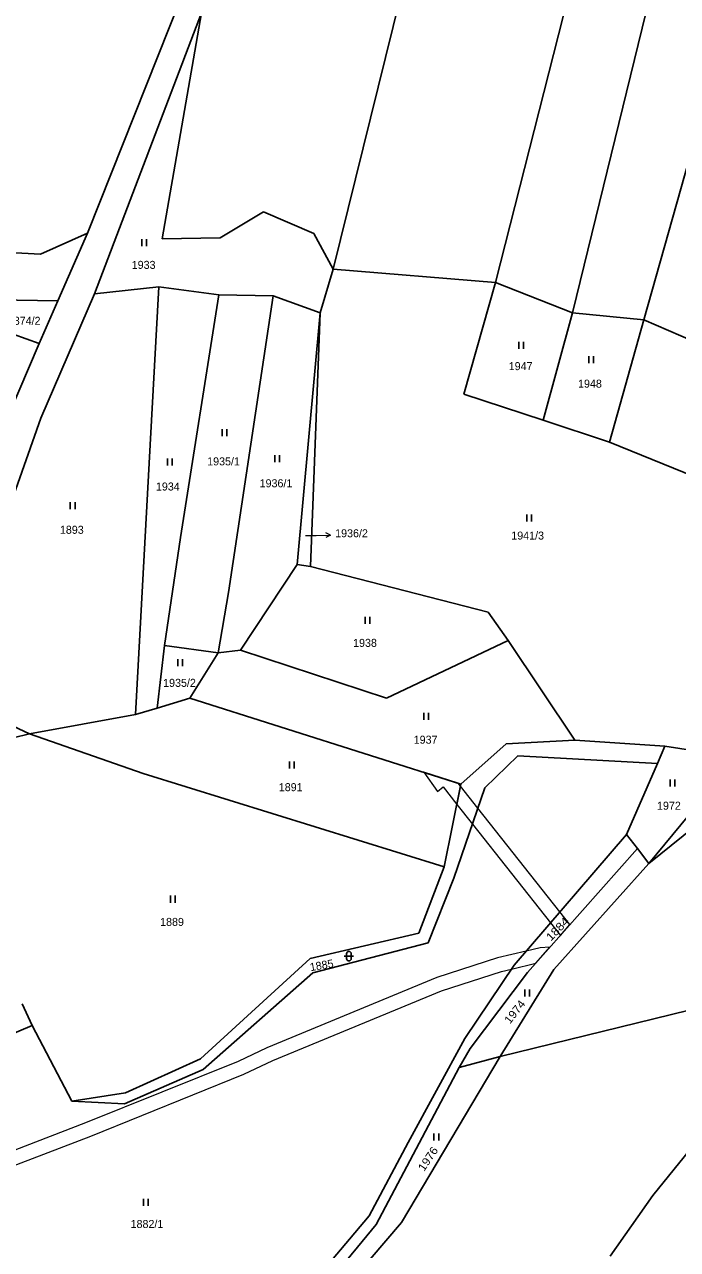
# Model space of a CAD drawing. Extents: x -820420 to -815896, y -1105820 to -1103643.
# Drawn here: x -817959 to -817820.3, y -1105443.7 to -1105183.5 of the extents above; entities that cross this region are included whole.
import ezdxf
from ezdxf.enums import TextEntityAlignment as Align

# ---------------------------------------------------------------- set-up
doc = ezdxf.new("R2010")
doc.units = 0
doc.header["$LTSCALE"] = 0.68
for name, color, linetype, lineweight in [('1', 7, 'Continuous', 25), ('13', 7, 'Continuous', 13), ('3', 7, 'Continuous', 25), ('7', 7, 'Continuous', 13)]:
    doc.layers.add(name, color=color, linetype=linetype, lineweight=lineweight)
doc.layers.add('2', color=7, linetype='Continuous')

msp = doc.modelspace()

# ---------------------------------------------------------------- linework, layer by layer
at = {"layer": '1'}
for p, q in [((-817869.71, -1105139.34), (-817893.45, -1105235.53)), ((-817911.24, -1105141.23), (-817945.61, -1105227.86)), ((-817821.32, -1105157.54), (-817842.63, -1105244.78)), ((-817858.96, -1105238.36), (-817841.26, -1105168.5)), ((-817944.12, -1105240.74), (-817921.42, -1105181.08)), ((-817921.42, -1105181.08), (-817929.76, -1105229.05)), ((-817827.46, -1105246.28), (-817810.28, -1105185.18)), ((-817917.43, -1105228.83), (-817908.24, -1105223.37)), ((-817908.24, -1105223.37), (-817897.54, -1105227.95)), ((-817955.63, -1105232.32), (-817945.61, -1105227.86)), ((-817945.61, -1105227.86), (-817951.93, -1105242.22)), ((-817929.76, -1105229.05), (-817917.43, -1105228.83)), ((-817897.54, -1105227.95), (-817893.45, -1105235.53)), ((-817973.59, -1105231.41), (-817955.63, -1105232.32)), ((-817893.45, -1105235.53), (-817896.18, -1105244.78)), ((-817893.45, -1105235.53), (-817858.96, -1105238.36)), ((-817930.44, -1105239.25), (-817944.12, -1105240.74)), ((-817932.31, -1105272.84), (-817930.44, -1105239.25)), ((-817917.7, -1105240.97), (-817930.44, -1105239.25)), ((-817865.72, -1105262.1), (-817858.96, -1105238.36)), ((-817858.96, -1105238.36), (-817842.63, -1105244.78)), ((-817951.93, -1105242.22), (-817984, -1105241.67)), ((-817955.85, -1105251.33), (-817951.93, -1105242.22)), ((-817955.55, -1105267.18), (-817944.12, -1105240.74)), ((-817917.7, -1105240.97), (-817925.86, -1105292.51)), ((-817906.21, -1105241.19), (-817917.7, -1105240.97)), ((-817906.21, -1105241.19), (-817915.66, -1105304.18)), ((-817896.18, -1105244.78), (-817906.21, -1105241.19)), ((-817901.09, -1105298.27), (-817896.18, -1105244.78)), ((-817898.25, -1105298.66), (-817896.18, -1105244.78)), ((-817842.63, -1105244.78), (-817848.88, -1105267.62)), ((-817842.63, -1105244.78), (-817827.46, -1105246.28)), ((-817827.46, -1105246.28), (-817834.79, -1105272.23)), ((-817827.46, -1105246.28), (-817795.47, -1105260.25)), ((-817964.22, -1105248.36), (-817955.85, -1105251.33)), ((-817964.57, -1105271.58), (-817955.85, -1105251.33)), ((-817848.88, -1105267.62), (-817865.72, -1105262.1)), ((-817955.55, -1105267.18), (-817968.42, -1105303.73)), ((-817834.79, -1105272.23), (-817848.88, -1105267.62)), ((-817935.41, -1105330.1), (-817932.31, -1105272.84)), ((-817804.94, -1105284.43), (-817834.79, -1105272.23)), ((-817925.86, -1105292.51), (-817929.3, -1105315.45)), ((-817913.14, -1105316.48), (-817901.09, -1105298.27)), ((-817898.25, -1105298.66), (-817901.09, -1105298.27)), ((-817898.25, -1105298.66), (-817860.52, -1105308.36)), ((-817915.66, -1105304.18), (-817917.89, -1105316.99)), ((-817860.52, -1105308.36), (-817856.31, -1105314.36)), ((-817856.31, -1105314.36), (-817882.12, -1105326.61)), ((-817856.31, -1105314.36), (-817842.12, -1105335.58)), ((-817929.3, -1105315.45), (-817930.79, -1105328.75)), ((-817929.3, -1105315.45), (-817917.89, -1105316.99)), ((-817917.89, -1105316.99), (-817923.89, -1105326.62)), ((-817917.89, -1105316.99), (-817913.14, -1105316.48)), ((-817882.12, -1105326.61), (-817913.14, -1105316.48)), ((-817923.89, -1105326.62), (-817930.79, -1105328.75)), ((-817866.31, -1105344.9), (-817923.89, -1105326.62)), ((-817957.96, -1105334.24), (-817968.34, -1105329.29)), ((-817935.41, -1105330.1), (-817957.96, -1105334.24)), ((-817930.79, -1105328.75), (-817935.41, -1105330.1)), ((-817977.63, -1105338.91), (-817957.96, -1105334.24)), ((-817957.96, -1105334.24), (-817933.78, -1105342.62)), ((-817856.74, -1105336.31), (-817842.12, -1105335.58)), ((-817842.12, -1105335.58), (-817823, -1105336.84)), ((-817866.31, -1105344.9), (-817856.74, -1105336.31)), ((-817797.31, -1105338.32), (-817826.4, -1105361.74)), ((-817824.6, -1105340.53), (-817823, -1105336.84)), ((-817823, -1105336.84), (-817812.7, -1105338.43)), ((-817854.26, -1105338.88), (-817861.26, -1105345.68)), ((-817824.6, -1105340.53), (-817854.26, -1105338.88)), ((-817831.13, -1105355.59), (-817824.6, -1105340.53)), ((-817933.78, -1105342.62), (-817869.85, -1105362.5)), ((-817869.85, -1105362.5), (-817866.31, -1105344.9)), ((-817861.26, -1105345.68), (-817867.79, -1105364.87)), ((-817814.49, -1105347.38), (-817826.4, -1105361.74)), ((-817831.13, -1105355.59), (-817855.04, -1105383.35)), ((-817828.85, -1105358.55), (-817831.13, -1105355.59)), ((-817852.2, -1105384.94), (-817828.85, -1105358.55)), ((-817826.4, -1105361.74), (-817828.85, -1105358.55)), ((-817846.59, -1105384.28), (-817826.4, -1105361.74)), ((-817875.28, -1105376.54), (-817869.85, -1105362.5)), ((-817867.79, -1105364.87), (-817873.31, -1105378.62)), ((-817898.34, -1105381.95), (-817875.28, -1105376.54)), ((-817873.31, -1105378.62), (-817897.8, -1105384.97)), ((-817921.6, -1105403.24), (-817898.34, -1105381.95)), ((-817897.8, -1105384.97), (-817921.06, -1105405.53)), ((-817855.04, -1105383.35), (-817865.52, -1105398.91)), ((-817864.33, -1105401.03), (-817852.2, -1105384.94)), ((-817782.25, -1105384.13), (-817857.97, -1105402.72)), ((-817857.97, -1105402.72), (-817846.59, -1105384.28)), ((-817959.52, -1105391.55), (-817957.4, -1105396.2)), ((-817970.34, -1105401.67), (-817957.4, -1105396.2)), ((-817957.4, -1105396.2), (-817948.98, -1105412.24)), ((-817865.52, -1105398.91), (-817877.52, -1105421.02)), ((-817866.7, -1105405.12), (-817864.33, -1105401.03)), ((-817937.55, -1105410.45), (-817921.6, -1105403.24)), ((-817857.97, -1105402.72), (-817878.93, -1105438.02)), ((-817857.97, -1105402.72), (-817866.7, -1105405.12)), ((-817921.06, -1105405.53), (-817937.76, -1105412.81)), ((-817884.31, -1105438.47), (-817866.7, -1105405.12)), ((-817948.98, -1105412.24), (-817937.55, -1105410.45)), ((-817825.59, -1105432.28), (-817807.78, -1105410.27)), ((-817937.76, -1105412.81), (-817948.98, -1105412.24)), ((-817877.52, -1105421.02), (-817885.84, -1105436.6)), ((-817834.63, -1105445.18), (-817825.59, -1105432.28)), ((-817885.84, -1105436.6), (-817905.34, -1105459.71)), ((-817913.51, -1105478.26), (-817878.93, -1105438.02)), ((-817902.19, -1105460), (-817884.31, -1105438.47))]:
    msp.add_line(p, q, dxfattribs=at)
at = {"layer": '13'}
for points in [[(-817871.27, -1105346.43), (-817870.1, -1105345.5), (-817867.18, -1105349.2), (-817866.4, -1105345.34), (-817866.9, -1105344.71), (-817874.22, -1105342.39)], [(-817847.3, -1105374.37), (-817845.2, -1105377.03), (-817843.18, -1105374.75), (-817845.31, -1105372.05), (-817862.73, -1105349.99), (-817866.4, -1105345.34), (-817867.18, -1105349.2), (-817863.88, -1105353.38)], [(-817906.26, -1105403.62), (-817870.42, -1105388.81), (-817857.72, -1105384.7), (-817855.6, -1105384.19), (-817850.44, -1105382.95), (-817847.44, -1105379.56), (-817849.48, -1105379.64), (-817852.45, -1105380.35), (-817858.54, -1105381.8), (-817871.44, -1105385.99), (-817907.52, -1105400.9), (-817913.62, -1105403.79), (-817946.01, -1105416.87), (-817970.85, -1105426.37), (-817990.71, -1105433.53), (-817989.76, -1105436.38), (-817969.79, -1105429.17), (-817944.93, -1105419.67), (-817912.4, -1105406.53)]]:
    msp.add_lwpolyline(points, close=True, dxfattribs=at)
at = {"layer": '3'}
for p, q in [((-817934.081, -1105230.62), (-817934.081, -1105229.12)), ((-817933.08, -1105230.62), (-817933.08, -1105229.12)), ((-817854.041, -1105252.45), (-817854.041, -1105250.95)), ((-817853.04, -1105252.45), (-817853.04, -1105250.95)), ((-817839.191, -1105255.51), (-817839.191, -1105254.01)), ((-817838.19, -1105255.51), (-817838.19, -1105254.01)), ((-817917.001, -1105270.97), (-817917.001, -1105269.47)), ((-817916, -1105270.97), (-817916, -1105269.47)), ((-817928.611, -1105277.24), (-817928.611, -1105275.74)), ((-817927.61, -1105277.24), (-817927.61, -1105275.74)), ((-817905.861, -1105276.54), (-817905.861, -1105275.04)), ((-817904.86, -1105276.54), (-817904.86, -1105275.04)), ((-817949.271, -1105286.53), (-817949.271, -1105285.03)), ((-817948.27, -1105286.53), (-817948.27, -1105285.03)), ((-817852.341, -1105289.13), (-817852.341, -1105287.63)), ((-817851.34, -1105289.13), (-817851.34, -1105287.63)), ((-817886.631, -1105310.84), (-817886.631, -1105309.34)), ((-817885.63, -1105310.84), (-817885.63, -1105309.34)), ((-817926.451, -1105319.86), (-817926.451, -1105318.36)), ((-817925.45, -1105319.86), (-817925.45, -1105318.36)), ((-817874.201, -1105331.24), (-817874.201, -1105329.74)), ((-817873.2, -1105331.24), (-817873.2, -1105329.74)), ((-817902.731, -1105341.59), (-817902.731, -1105340.09)), ((-817901.73, -1105341.59), (-817901.73, -1105340.09)), ((-817821.871, -1105345.4), (-817821.871, -1105343.9)), ((-817820.87, -1105345.4), (-817820.87, -1105343.9)), ((-817928.011, -1105370.08), (-817928.011, -1105368.58)), ((-817927.01, -1105370.08), (-817927.01, -1105368.58)), ((-817891.121, -1105381.441), (-817889.119, -1105381.441)), ((-817890.621, -1105380.941), (-817890.621, -1105381.942)), ((-817889.619, -1105381.942), (-817889.619, -1105380.941)), ((-817852.741, -1105389.99), (-817852.741, -1105388.49)), ((-817851.74, -1105389.99), (-817851.74, -1105388.49)), ((-817872.041, -1105420.59), (-817872.041, -1105419.09)), ((-817871.04, -1105420.59), (-817871.04, -1105419.09)), ((-817933.731, -1105434.45), (-817933.731, -1105432.95)), ((-817932.73, -1105434.45), (-817932.73, -1105432.95))]:
    msp.add_line(p, q, dxfattribs=at)
for centre, start, end in [((-817890.12, -1105380.9409), 0, 180), ((-817890.12, -1105381.9409), 180, 359.98789)]:
    msp.add_arc(centre, 0.5, start, end, dxfattribs=at)
at = {"layer": '7'}
msp.add_line((-817894.029, -1105292.018), (-817895.04, -1105291.534), dxfattribs=at)
msp.add_lwpolyline([(-817899.35, -1105292.1), (-817897.03, -1105292.07), (-817894.029, -1105292.018), (-817895.022, -1105292.536)], dxfattribs=at)

# ---------------------------------------------------------------- texts
at = {"layer": '2'}
for s, p in [('1933', (-817933.7, -1105235.455)), ('1874/2', (-817959.07, -1105247.335)), ('1947', (-817853.64, -1105256.965)), ('1948', (-817838.92, -1105260.685)), ('1935/1', (-817916.73, -1105277.195)), ('1934', (-817928.56, -1105282.535)), ('1936/1', (-817905.59, -1105281.845)), ('1893', (-817948.95, -1105291.725)), ('1941/3', (-817852.15, -1105292.955)), ('1938', (-817886.69, -1105315.745)), ('1935/2', (-817926.08, -1105324.235)), ('1937', (-817873.82, -1105336.315)), ('1891', (-817902.47, -1105346.395)), ('1972', (-817822.15, -1105350.335)), ('1889', (-817927.67, -1105375.015)), ('1882/1', (-817932.99, -1105439.175))]:
    msp.add_text(s, height=1.7, dxfattribs=at).set_placement(p, align=Align.CENTER)
msp.add_text('1936/2', height=1.7, dxfattribs=at).set_placement((-817893.03, -1105292.465))
for s, rotation, width, p in [('1884', 46, 1.15, (-817845.193, -1105376.2635)), ('1974', 52, 1.1, (-817854.2166, -1105393.7948)), ('1976', 56, 1.1, (-817872.6039, -1105424.9748))]:
    msp.add_text(s, height=1.7, rotation=rotation, dxfattribs=dict(at, width=width)).set_placement(p, align=Align.CENTER)
msp.add_text('1885', height=1.7, rotation=10, dxfattribs=at).set_placement((-817895.7506, -1105384.2049), align=Align.CENTER)

doc.saveas('drawing.dxf')
